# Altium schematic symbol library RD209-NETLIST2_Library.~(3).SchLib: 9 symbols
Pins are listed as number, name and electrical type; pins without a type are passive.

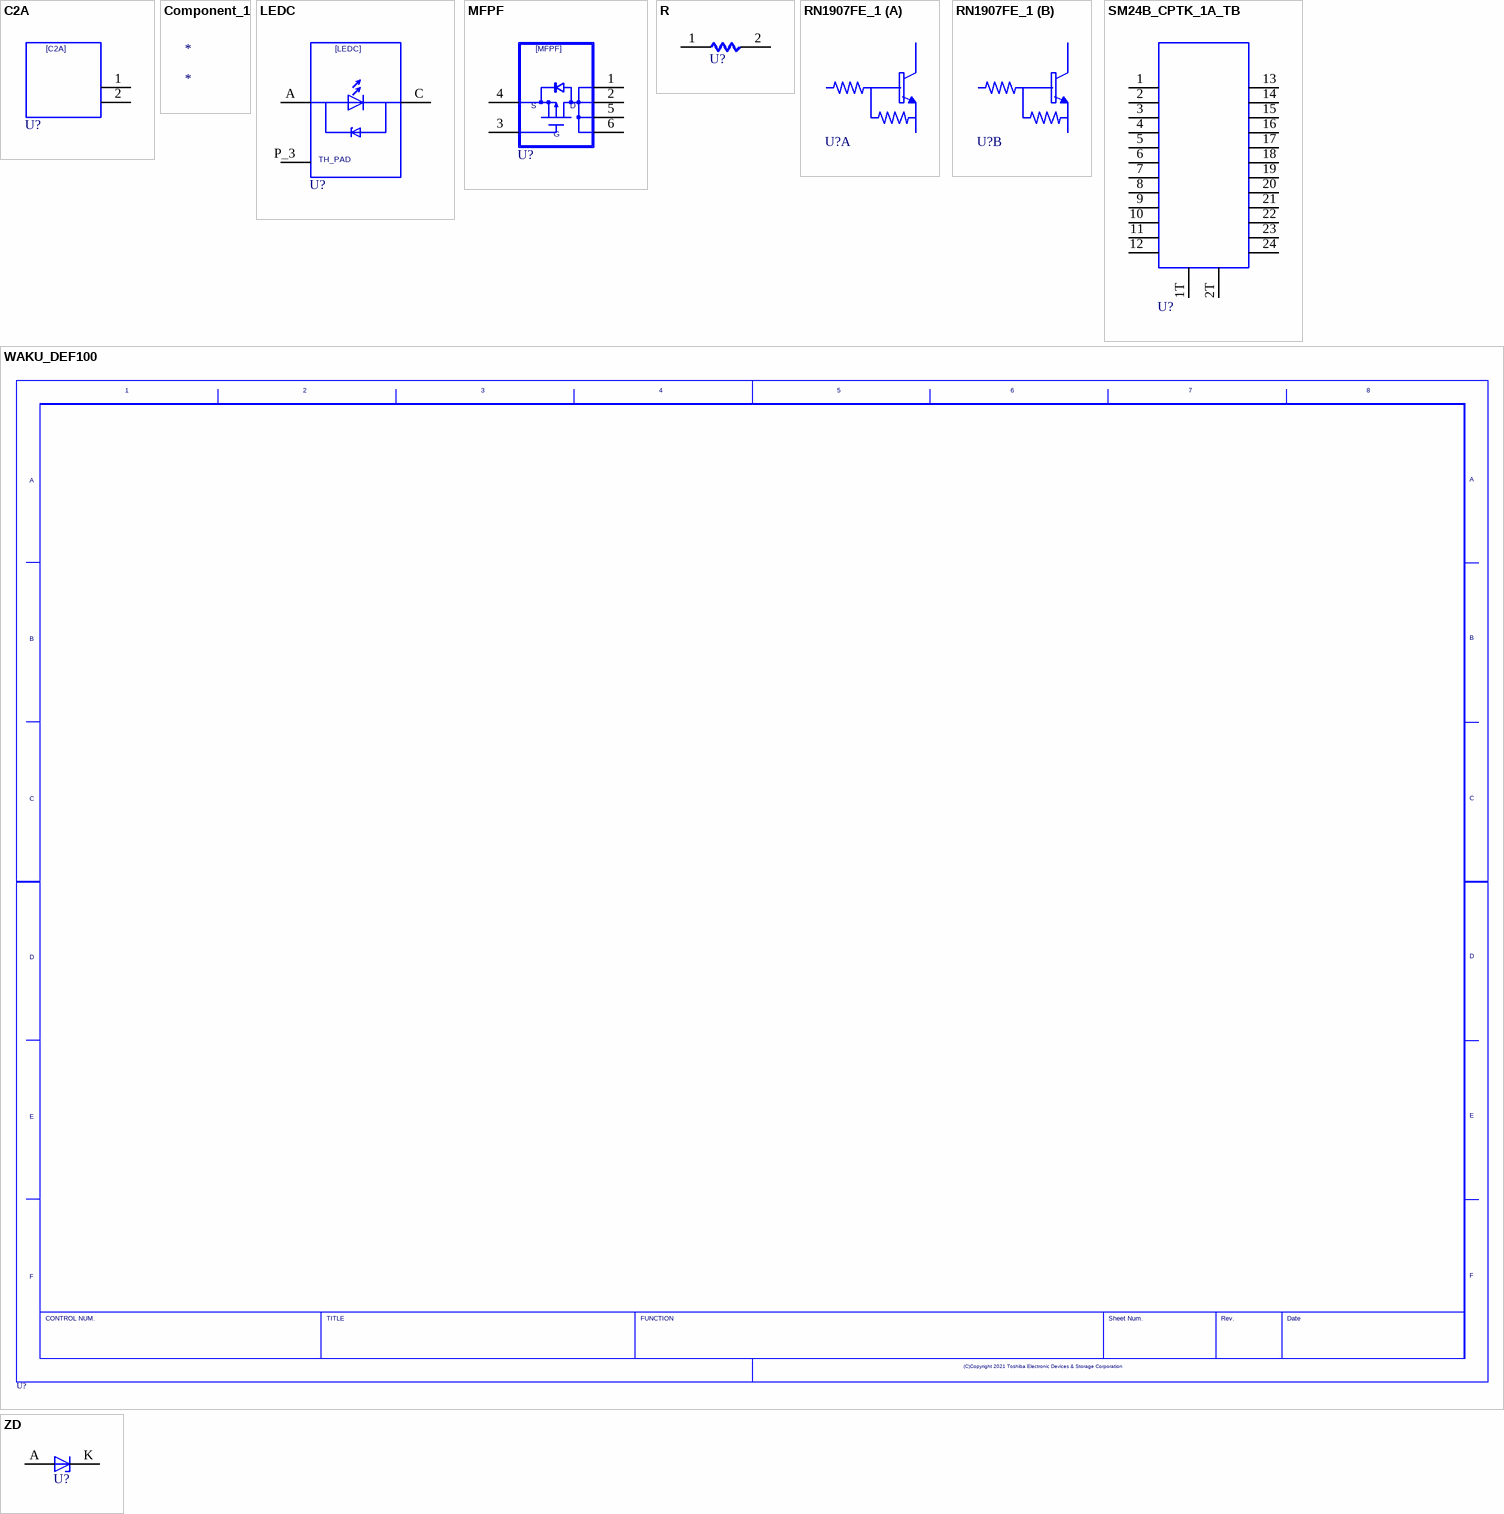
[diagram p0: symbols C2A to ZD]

## C2A
designator U?  (value not drawn)
SAVEAREA0: -4611,-206,24632,18258; SAVECOUNT: 25; TIME: 13:28:28; UPDATEUSER: tomizawa-y; UPDATETIME: 12:08:31; OriginalSymbolOrigin: (2540,15240); Altium-Right: 50
pins: 1, 2

## Component_1
designator *

## LEDC
designator U?  (value not drawn)
SAVEAREA0: -10936,-329,35896,28705; TIME: 14:49:55; UPDATEUSER: fukuda-y; UPDATETIME: 15:53:51; SAVECOUNT: 15; OriginalSymbolOrigin: (5080,25400); Altium-Right: 60; Altium-Bottom: 90
pins: A, C, P_3 NC

## MFPF
designator U?  (value not drawn)
SAVECOUNT: 11; SAVEAREA0: -6011,0,28984,22860; OriginalSymbolOrigin: (5080,20320); Altium-Right: 50; Altium-Bottom: 70
pins: 1, 2, 3, 4, 5, 6

## R
designator U?  (value not drawn)
OriginalSymbolOrigin: (5080,5080); Altium-Right: 20
pins: 1, 2

## RN1907FE_1
designator U?  (value not drawn)
TIME: 08:46:53; UPDATEUSER: t5459927; UPDATETIME: 14:30:50; SAVECOUNT: 6; SAVEAREA0: -3836,-13019,18528,3377; OriginalSymbolOrigin: (0,5080); Altium-Right: 60; Altium-Bottom: 80
part A pins: 1, 2, 6
part B pins: 3, 4, 5

## SM24B_CPTK_1A_TB
designator U?  (value not drawn)
TIME: 12:18:04; UPDATEUSER: t5459927; UPDATETIME: 10:12:38; SAVECOUNT: 3; SAVEAREA0: -83685,-38329,109566,68648; OriginalSymbolOrigin: (5080,43180); Altium-Right: 60; Altium-Bottom: 150
pins: 1, 1T, 2, 2T, 3, 4, 5, 6, 7, 8, 9, 10, 11, 12, 13, 14, 15, 16, 17, 18, 19, 20, 21, 22, 23, 24

## WAKU_DEF100
designator U?  (value not drawn)
PLOTTIME: HH:MM; SAVEAREA0: 148187,-66180,486823,89919; TIME: 14:30:25; UPDATEUSER: t5459927; UPDATETIME: 11:46:11; SAVECOUNT: 6; OriginalSymbolOrigin: (10160,284480); Altium-Right: 1570; Altium-Bottom: 1070

## ZD
designator U?  (value not drawn)
SAVEAREA0: -4630,-153,17114,13055; TIME: 14:49:55; UPDATEUSER: fukuda-y; UPDATETIME: 08:18:42; SAVECOUNT: 6; OriginalSymbolOrigin: (5080,5080); Altium-Right: 10; Altium-Bottom: 20
pins: A, K C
